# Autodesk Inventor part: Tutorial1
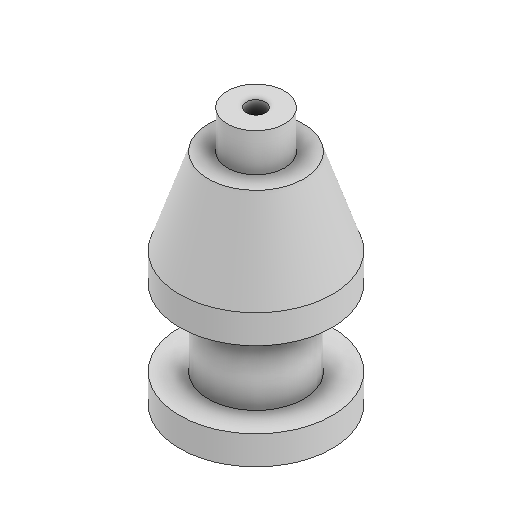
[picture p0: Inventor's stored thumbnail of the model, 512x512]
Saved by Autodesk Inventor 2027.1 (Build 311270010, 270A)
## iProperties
Created: 2022-07
Part Number: Tutorial1
Material: Generic
Document SubType Name: Modeling
Designer: LENOVO-CADCIM
Density: 1 g/cm^3
Appearance: Default
Author: LENOVO-CADCIM
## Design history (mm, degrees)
sketch "Sketch1"
  geometry: L1 (10, 0)-(10, 270); L2 (10, 270)-(30, 270); L3 (30, 270)-(30, 230); L4 (30, 230)-(50, 230); L5 (50, 230)-(80, 140); L6 (80, 140)-(80, 110); L7 (80, 110)-(50, 110); L8 (50, 110)-(50, 30); L9 (50, 30)-(80, 30); L10 (80, 30)-(80, 0); L11 (80, 0)-(10, 0); L12 (0, 0)-(0, 270)
  constraints: 24 end point, 8 perpendicular, 2 vertical, 1 collinear, 1 parallel, 1 point on line
  dimensions: "d0" = 30 distance between parallel lines of L11 L9; "d1" = 80 distance between parallel lines of L7 L9; "d2" = 30 distance of L5.end L6.end; "d3" = 230 distance between parallel lines of L4 L11; "d4" = 40 distance between parallel lines of L4 L2; "d6" = 160 diameter of L10.end L12; "d7" = 100 diameter of L8 L12; "d8" = 20 diameter of L1 L12; "d9" = 60 diameter of L3 L12; "d10" = 100 diameter of L4.end L12
revolve "Revolution1" sketch "Sketch1" stored, may be unused: angle "d11" = 90 deg
body "Solid1"
